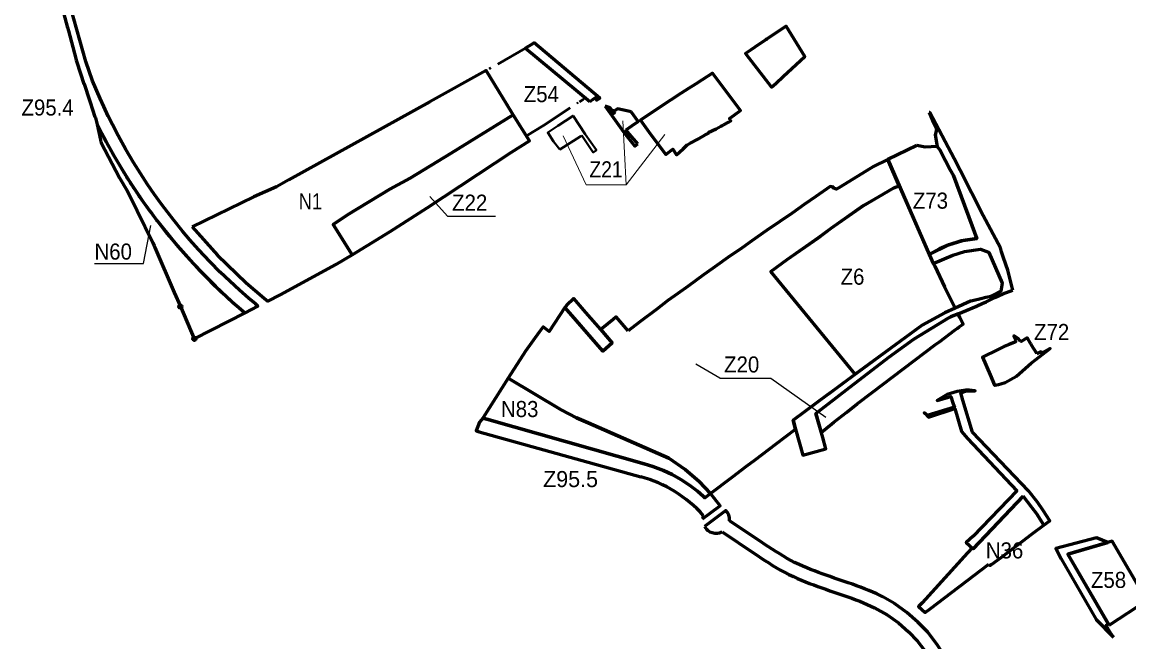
# Model space of a CAD drawing. Extents: x -650277 to -643422, y -1073980 to -1066720.
# Drawn here: x -649120 to -647467, y -1071620 to -1070696 of the extents above; entities that cross this region are included whole.
import ezdxf

# ---------------------------------------------------------------- set-up
doc = ezdxf.new("R2010")
doc.units = 0
doc.header["$LTSCALE"] = 9.6
doc.header["$PDMODE"] = 32
doc.header["$PDSIZE"] = 4.8
doc.linetypes.add('DOT_DASHED', pattern=[7.7, 5, -1.2, 0.3, -1.2])
for name, color, linetype, lineweight in [('1', 7, 'Continuous', 60), ('15', 7, 'Continuous', 60), ('18', 7, 'Continuous', 60), ('42', 7, 'Continuous', 60), ('60', 7, 'Continuous', 60), ('63', 7, 'Continuous', 25), ('7', 7, 'Continuous', 60), ('9', 7, 'Continuous', 60)]:
    doc.layers.add(name, color=color, linetype=linetype, lineweight=lineweight)

msp = doc.modelspace()

# ---------------------------------------------------------------- linework, layer by layer
at = {"layer": '1'}
for points in [[(-648032.601, -1070737.472), (-648039.82, -1070742.33), (-648000.85, -1070792.88), (-647994.63, -1070787.05), (-647982.89, -1070776.05), (-647976.97, -1070770.51), (-647964.21, -1070758.77), (-647951.11, -1070746.78), (-647979.17, -1070701.65), (-648008.28, -1070720.96), (-648009.29, -1070721.79), (-648019.49, -1070728.65)], [(-648540.7, -1070928.6), (-648571.14, -1070944.67), (-648634.07, -1070983.17), (-648655.76, -1070997.5), (-648627.39, -1071042.65), (-648605.3, -1071029.34), (-648570.23, -1071008.2), (-648515.46, -1070972.94), (-648389.33, -1070889.79), (-648362.519, -1070872.788), (-648386.587, -1070833.807), (-648479.18, -1070891.26)], [(-648215.08, -1071156.35), (-648232.8, -1071135.6), (-648237.46, -1071139.38), (-648245.49, -1071145.91), (-648256.04, -1071154.5), (-648238.84, -1071174.33), (-648253.126, -1071186.542), (-648292.587, -1071141.054), (-648309.41, -1071121.655), (-648333.002, -1071157.07), (-648341.943, -1071150.071), (-648347.949, -1071158.385), (-648368.48, -1071186.81), (-648394.104, -1071227.17), (-648315.127, -1071274.052), (-648292.406, -1071286.112), (-648274.918, -1071293.751), (-648154.21, -1071346.477), (-648130, -1071363), (-648109, -1071381), (-648091.92, -1071399.07), (-648060.01, -1071374.69), (-648038.18, -1071358.51), (-648025.39, -1071348.76), (-647994.31, -1071325.03), (-647965.26, -1071302.86), (-647966.226, -1071299.385), (-647968.896, -1071289.779), (-647916.208, -1071250.662), (-647895.959, -1071235.746), (-647875.939, -1071221.104), (-648001.922, -1071067.83), (-647977.41, -1071049.74), (-647930.96, -1071017.383), (-647912.11, -1071003.11), (-647864.29, -1070969.503), (-647818.33, -1070942.91), (-647810.243, -1070939.825), (-647827.527, -1070900.351), (-647848.89, -1070911.21), (-647897.76, -1070941.62), (-647904.13, -1070944.78), (-647909.42, -1070942.63), (-647908.63, -1070942.1), (-647913.45, -1070940.79), (-647934.9, -1070955.87), (-647952.01, -1070967.82), (-647970.19, -1070980.45), (-647988.81, -1070993.27), (-648008.34, -1071006.32), (-648030.24, -1071021.91), (-648044.82, -1071032.25), (-648051.48, -1071036.97), (-648062.53, -1071044.59), (-648085.73, -1071060.92), (-648097.61, -1071069.37), (-648102.55, -1071072.86), (-648125.53, -1071089.51), (-648141.12, -1071100.71), (-648155.77, -1071111.23), (-648172.48, -1071123.95), (-648197.57, -1071143.03)], [(-648001.922, -1071067.83), (-647977.41, -1071049.74), (-647930.7, -1071017.18), (-647911.838, -1071002.919), (-647864.03, -1070969.3), (-647864.03, -1070969.3), (-647818.33, -1070942.91), (-647810.243, -1070939.825), (-647759.52, -1071055.67), (-647757.19, -1071059.66), (-647742.64, -1071090.72), (-647726.74, -1071122.48), (-647742.35, -1071129.43), (-647775.982, -1071148.001), (-647775.982, -1071148.001), (-647875.939, -1071221.104)], [(-647756.03, -1071176.76), (-647750.34, -1071172.5), (-647726.56, -1071154.68), (-647723.79, -1071152.61), (-647720.85, -1071150.41), (-647714.71, -1071146.51), (-647719.73, -1071136.48), (-647722.51, -1071130.93), (-647732.58, -1071135.04), (-647733.38, -1071135.37), (-647737.027, -1071137.593), (-647761.366, -1071152.304), (-647788.66, -1071168.8), (-647826.56, -1071195.86), (-647889.22, -1071244.48), (-647915.6, -1071264.95), (-647934.6, -1071279.45), (-647926.69, -1071307.81), (-647910.73, -1071295.08), (-647907.92, -1071292.84), (-647888.77, -1071277.56), (-647873.25, -1071265.17), (-647850.956, -1071248.208)]]:
    msp.add_lwpolyline(points, close=True, dxfattribs=at)
at = {"layer": '1', "linetype": 'DOT_DASHED', "lineweight": 40}
msp.add_lwpolyline([(-648368.163, -1070734.376), (-648427.25, -1070767.95), (-648366.98, -1070865.44), (-648341.58, -1070849.98), (-648287.74, -1070814.32), (-648282.44, -1070810.84), (-648278.832, -1070808.761)], close=True, dxfattribs=at)
at = {"layer": '1'}
for points in [[(-648095.42, -1070860.3), (-648083.65, -1070854.89), (-648076.73, -1070851.07), (-648074.41, -1070849.79), (-648072.59, -1070848.79), (-648065.35, -1070844.8), (-648061.52, -1070842.68), (-648063.76, -1070839.49), (-648056.61, -1070834.26), (-648047.17, -1070827.35), (-648089.27, -1070771.57), (-648104.78, -1070781.65), (-648114.77, -1070788.08), (-648125.2, -1070794.79), (-648136.08, -1070801.79)], [(-648136.08, -1070801.79), (-648151.77, -1070812.11), (-648167.6, -1070822.53), (-648196.65, -1070841.7), (-648181.75, -1070862.74), (-648158.58, -1070892.98), (-648148.34, -1070884.92), (-648142.79, -1070893.78), (-648133.14, -1070884.6), (-648127, -1070878.75), (-648122.72, -1070876.44), (-648111.24, -1070870.11), (-648099.85, -1070863.82), (-648094.9, -1070861.09), (-648095.42, -1070860.3)], [(-648237.46, -1070829.68), (-648241.96, -1070823.46), (-648249.5, -1070821.08)], [(-648249.5, -1070821.08), (-648222.158, -1070859.221), (-648217.1, -1070865.56), (-648205.18, -1070880.5), (-648200.86, -1070877.05)], [(-648210.517, -1070829.445), (-648221.58, -1070827.03), (-648231.22, -1070824.92), (-648237.46, -1070829.68)], [(-648218.11, -1070856.44), (-648209.37, -1070850.44), (-648200.17, -1070844.094), (-648210.517, -1070829.445)], [(-648200.86, -1070877.05), (-648212.94, -1070862.74), (-648217.85, -1070856.93), (-648218.11, -1070856.44)]]:
    msp.add_lwpolyline(points, dxfattribs=at)
at = {"layer": '1', "lineweight": 40}
for points in [[(-648284.02, -1070864.91), (-648267.24, -1070889.9), (-648262.4, -1070886.58), (-648279.39, -1070862.98), (-648297.39, -1070835.36), (-648320.02, -1070850.16), (-648335.19, -1070860.49), (-648326.41, -1070873.55), (-648317.14, -1070885.48)], [(-648317.14, -1070885.48), (-648285.72, -1070865.96), (-648284.02, -1070864.91)]]:
    msp.add_lwpolyline(points, dxfattribs=at)
at = {"layer": '1', "lineweight": 13}
for points in [[(-648223, -1070843), (-648217.945, -1070938.322), (-648277.841, -1070938.322), (-648311.985, -1070865.23)], [(-648277.841, -1070938.322), (-648217.945, -1070938.322), (-648160.135, -1070863.066)]]:
    msp.add_lwpolyline(points, dxfattribs=at)
at = {"layer": '1'}
msp.add_point((-648237.46, -1070829.68), dxfattribs=at)
at = {"layer": '15'}
msp.add_line((-648272.453, -1070814.072), (-648271.1, -1070813.17), dxfattribs=at)
for points in [[(-648271.1, -1070813.17), (-648267.8, -1070810.96), (-648264.38, -1070808.66), (-648262.15, -1070811.96), (-648257.61, -1070808.91), (-648355.275, -1070726.455), (-648360.83, -1070729.87), (-648366.739, -1070733.501), (-648368.163, -1070734.376), (-648272.453, -1070814.072)], [(-647659.01, -1071032.66), (-647685.1, -1070983.93), (-647719.06, -1070916.45), (-647728.35, -1070899.11), (-647764.84, -1070830.47), (-647765.72, -1070830.64)], [(-647765.72, -1070830.64), (-647759.08, -1070845.74), (-647755.87, -1070853.02), (-647754.6, -1070856.11), (-647756.45, -1070863.95), (-647753.81, -1070881.3)], [(-647753.81, -1070881.3), (-647749.75, -1070886.1), (-647734.48, -1070915.94), (-647729.27, -1070924.35), (-647701.45, -1070999.4)], [(-647701.45, -1070999.4), (-647694.54, -1071018.549), (-647718, -1071022), (-647736, -1071028), (-647750, -1071034), (-647765.408, -1071042.223), (-647759.52, -1071055.67), (-647730.17, -1071043.21), (-647712.74, -1071037.99), (-647688.9, -1071034.18), (-647676.96, -1071039.014)], [(-647676.96, -1071039.014), (-647676.9, -1071039.03), (-647676.45, -1071039.22), (-647656.443, -1071085.369), (-647658.55, -1071097.02), (-647669.02, -1071102.33), (-647667.35, -1071106.38), (-647655.47, -1071100.98), (-647640.727, -1071095.819)], [(-647640.727, -1071095.819), (-647648.106, -1071065.551), (-647654.747, -1071047.095), (-647657.699, -1071038.232), (-647659.01, -1071032.66)], [(-647498.271, -1071593.544), (-647558.654, -1071489.738), (-647498.8, -1071471.94), (-647515.87, -1071465.25), (-647576.471, -1071481.091), (-647568.35, -1071496.656), (-647516.376, -1071586.89), (-647490.561, -1071613.609)], [(-647490.561, -1071613.609), (-647493.6, -1071608.5), (-647501.11, -1071595.45), (-647498.271, -1071593.544)]]:
    msp.add_lwpolyline(points, dxfattribs=at)
for points in [[(-647734.48, -1070915.94), (-647741.21, -1070902.78), (-647749.75, -1070886.1)], [(-647826.56, -1071195.86), (-647788.66, -1071168.8), (-647761.366, -1071152.304), (-647737.027, -1071137.593), (-647733.38, -1071135.37), (-647732.58, -1071135.04), (-647722.51, -1071130.93), (-647716.51, -1071128.48), (-647695.08, -1071119.72), (-647685.55, -1071115.14), (-647684.15, -1071114.47), (-647680.64, -1071112.77), (-647667.35, -1071106.38), (-647669.02, -1071102.33), (-647674.17, -1071104.97), (-647675.64, -1071105.71), (-647680.82, -1071106.54), (-647688.45, -1071108.38), (-647701.04, -1071111.41), (-647703.96, -1071112.11), (-647726.74, -1071122.48), (-647742.35, -1071129.43), (-647775.982, -1071148.001), (-647895.959, -1071235.746), (-647916.161, -1071250.628), (-647916.208, -1071250.662), (-647968.896, -1071289.779), (-647965.26, -1071302.86), (-647954.38, -1071342), (-647934.51, -1071336.37), (-647919.88, -1071332.23), (-647924.53, -1071315.55), (-647934.6, -1071279.45), (-647915.6, -1071264.95), (-647889.22, -1071244.48)], [(-648238.84, -1071174.33), (-648256.04, -1071154.5), (-648278.39, -1071128.74), (-648296.34, -1071108.04), (-648307.33, -1071118.47), (-648309.41, -1071121.655), (-648292.587, -1071141.054), (-648270.236, -1071166.815), (-648253.126, -1071186.542)], [(-647625.428, -1071403.267), (-647612.269, -1071419.742), (-647605.292, -1071428.816), (-647594.43, -1071446.543), (-647585.273, -1071440.044), (-647595.335, -1071424.564), (-647603.9, -1071412.1), (-647617.49, -1071394.901), (-647700.816, -1071307.512), (-647715.355, -1071259.885), (-647718.342, -1071248.972), (-647711.447, -1071246.332), (-647696.81, -1071245.79), (-647705.59, -1071245.08), (-647710.94, -1071244.65), (-647723.57, -1071246.66), (-647738.56, -1071251.13), (-647753.647, -1071260.178), (-647733.15, -1071254.081), (-647729.795, -1071265.066), (-647728.006, -1071269.975), (-647768.445, -1071282.6), (-647772.97, -1071278.43), (-647772.07, -1071279.33), (-647766.35, -1071285.11), (-647727.368, -1071272.362), (-647717.363, -1071306.29), (-647708.429, -1071316.821), (-647634.524, -1071394.901), (-647700.078, -1071462.96), (-647710.546, -1071472.023), (-647699.767, -1071481.617)]]:
    msp.add_lwpolyline(points, close=True, dxfattribs=at)
at = {"layer": '18'}
for points in [[(-647783.95, -1070879.58), (-647827.363, -1070900.725), (-647765.408, -1071042.223), (-647736, -1071028), (-647715.488, -1071021.631)], [(-647783.95, -1070879.58), (-647827.363, -1070900.725), (-647765.408, -1071042.223), (-647736, -1071028), (-647715.488, -1071021.631)], [(-647715.488, -1071021.631), (-647694.54, -1071018.549), (-647701.45, -1070999.4), (-647729.27, -1070924.35), (-647734.48, -1070915.94), (-647749.75, -1070886.1), (-647753.81, -1070881.3), (-647771.47, -1070882.27), (-647783.95, -1070879.58)], [(-647715.488, -1071021.631), (-647694.54, -1071018.549), (-647701.45, -1070999.4), (-647729.27, -1070924.35), (-647734.48, -1070915.94), (-647749.75, -1070886.1), (-647753.81, -1070881.3), (-647771.47, -1070882.27), (-647783.95, -1070879.58)]]:
    msp.add_lwpolyline(points, dxfattribs=at)
at = {"layer": '42'}
for p, q in [((-648883.73, -1071120.13), (-648862.97, -1071168.09)), ((-648862.97, -1071168.09), (-648787.207, -1071129.363))]:
    msp.add_line(p, q, dxfattribs=at)
for points in [[(-649002.97, -1070857.609), (-649007.885, -1070848.153), (-649003.1, -1070871.35), (-649002.82, -1070872.69), (-649002.62, -1070873.69), (-649002.15, -1070875.96), (-648974.4, -1070927.77), (-648963.5, -1070946.45), (-648959.92, -1070953.73), (-648948.29, -1070977.37), (-648924.92, -1071024.89), (-648922.98, -1071029.49), (-648921.87, -1071032.04), (-648892.82, -1071099.15), (-648883.73, -1071120.13)], [(-648994.42, -1070874.053), (-648994.464, -1070873.974), (-648994.52, -1070873.867)], [(-648982.403, -1070895.812), (-648982.467, -1070895.704), (-648982.524, -1070895.601)], [(-648970.64, -1070915.778), (-648970.712, -1070915.663), (-648970.771, -1070915.564)], [(-648960.194, -1070932.542), (-648960.268, -1070932.429), (-648960.34, -1070932.313)], [(-648949.345, -1070949.096), (-648949.389, -1070949.031), (-648949.428, -1070948.972)], [(-648939.179, -1070963.89), (-648939.232, -1070963.818), (-648939.33, -1070963.675)], [(-648918.464, -1070992.141), (-648918.601, -1070991.969), (-648918.737, -1070991.784)], [(-648292.406, -1071286.112), (-648315.127, -1071274.052), (-648394.104, -1071227.17), (-648432.093, -1071286.645)], [(-648432.093, -1071286.645), (-648426.18, -1071288.32), (-648191.25, -1071354.858)], [(-648091.92, -1071399.07), (-648109, -1071381), (-648130, -1071363), (-648154.21, -1071346.477), (-648274.918, -1071293.751), (-648292.406, -1071286.112)], [(-648191.25, -1071354.858), (-648178.158, -1071358.781), (-648162.084, -1071364.918), (-648149.571, -1071370.788), (-648136.263, -1071378.194), (-648123.313, -1071386.696), (-648111.646, -1071395.618), (-648103.268, -1071402.88), (-648100.438, -1071405.517), (-648091.92, -1071399.07)], [(-647625.428, -1071403.267), (-647699.767, -1071481.617), (-647701.415, -1071480.15), (-647708.18, -1071487.57), (-647776.13, -1071562.1)], [(-647676.51, -1071504.34), (-647674.28, -1071506.59), (-647656.27, -1071493.04), (-647626.7, -1071470.46), (-647611.82, -1071459.38), (-647594.43, -1071446.543), (-647605.292, -1071428.816), (-647612.269, -1071419.742), (-647625.428, -1071403.267)], [(-647776.13, -1071562.1), (-647781.31, -1071567.79), (-647771.717, -1071576.551), (-647764.23, -1071571.01), (-647676.51, -1071504.34)]]:
    msp.add_lwpolyline(points, dxfattribs=at)
for start, end in [(206.85611, 208.07207), (208.08607, 209.71957), (209.73567, 211.25686), (211.27351, 212.56631), (212.58435, 213.8879), (213.89777, 215.07157), (215.08899, 217.38409), (217.41391, 230.04071)]:
    msp.add_arc((-648232.695, -1070467.567), 863.398, start, end, dxfattribs=at)
for p in [(-648883.73, -1071120.13), (-648862.97, -1071168.09)]:
    msp.add_point(p, dxfattribs=at)
at = {"layer": '60'}
for points in [[(-649068.65, -1070642.23), (-649054.31, -1070696.44), (-649052.77, -1070702.25), (-649052.44, -1070703.48), (-649051.03, -1070708.74), (-649040.03, -1070750.06), (-649039.38, -1070752.51), (-649039.06, -1070753.72), (-649038.51, -1070755.38), (-649027.74, -1070787.51), (-649027.64, -1070787.8), (-649019.48, -1070812.18), (-649018.48, -1070815.18), (-649011.24, -1070836.79), (-649010.67, -1070838.5), (-649007.885, -1070848.153), (-648994.464, -1070873.974), (-648982.467, -1070895.704), (-648970.712, -1070915.663), (-648960.268, -1070932.429), (-648949.389, -1070949.031), (-648939.232, -1070963.818), (-648918.601, -1070991.969), (-648896.068, -1071020.184), (-648886.874, -1071031.044), (-648874.793, -1071044.773), (-648863.847, -1071056.723), (-648851.175, -1071069.886), (-648838.696, -1071082.562), (-648823.087, -1071097.562), (-648816.379, -1071103.782), (-648806.239, -1071112.938), (-648797, -1071121), (-648790.23, -1071126.818), (-648787.207, -1071129.363), (-648767.824, -1071119.455), (-648771.725, -1071116.233), (-648781.806, -1071107.721), (-648795.407, -1071095.8), (-648824.292, -1071068.677), (-648839.273, -1071053.556), (-648856.883, -1071034.761), (-648869.629, -1071020.411), (-648880.44, -1071007.703), (-648894.164, -1070990.806), (-648902.714, -1070979.812), (-648912.396, -1070966.893), (-648922.92, -1070952.242), (-648932.78, -1070937.887), (-648943.414, -1070921.659), (-648953.605, -1070905.299), (-648965.093, -1070885.794), (-648976.834, -1070864.527), (-648985.145, -1070848.538), (-648991.386, -1070835.954), (-648998.132, -1070821.723), (-649003.641, -1070809.566), (-649014.888, -1070782.994), (-649025.129, -1070754.377), (-649047.11, -1070674.743)], [(-648103.894, -1071436.836), (-648079.108, -1071418.564), (-648077.53, -1071417.4), (-648091.92, -1071399.07), (-648100.438, -1071405.517), (-648103.268, -1071402.88), (-648111.646, -1071395.618), (-648123.313, -1071386.696), (-648136.263, -1071378.194), (-648149.571, -1071370.788), (-648162.084, -1071364.918), (-648178.158, -1071358.781), (-648191.25, -1071354.858), (-648426.18, -1071288.32), (-648432.093, -1071286.645), (-648437.16, -1071292.53), (-648442.191, -1071305.453), (-648437.454, -1071306.778), (-648196.236, -1071374.226)], [(-648063.593, -1071439.723), (-648063.862, -1071435.078), (-648064.838, -1071431.28), (-648066.623, -1071427.592), (-648069.022, -1071424.443), (-648101.203, -1071448.31)], [(-648101.203, -1071448.31), (-648098.259, -1071452.196), (-648096.014, -1071454.192), (-648093.059, -1071456.066), (-648089.539, -1071457.489), (-648085.585, -1071458.248), (-648081.642, -1071458.215), (-648078.539, -1071457.636), (-648074.86, -1071456.248)], [(-647834.953, -1071553.406), (-647837.929, -1071551.872), (-647843.891, -1071549), (-647849.898, -1071546.282), (-647855.937, -1071543.707), (-647861.998, -1071541.254), (-647868.073, -1071538.911), (-647874.155, -1071536.658), (-647880.233, -1071534.48), (-647886.305, -1071532.36), (-647892.363, -1071530.282), (-647901.28, -1071527.249), (-647907.294, -1071525.204), (-647913.282, -1071523.152), (-647919.238, -1071521.081), (-647925.157, -1071518.976), (-647931.035, -1071516.824), (-647936.866, -1071514.613), (-647942.644, -1071512.329), (-647948.363, -1071509.96), (-647954.016, -1071507.496), (-647959.792, -1071504.833), (-647966.547, -1071501.883), (-647972.035, -1071499.009), (-647977.67, -1071495.885), (-647983.266, -1071492.628), (-647988.829, -1071489.259), (-647994.366, -1071485.79), (-647999.887, -1071482.241), (-648005.399, -1071478.627), (-648010.917, -1071474.963), (-648016.446, -1071471.268), (-648063.593, -1071439.723)], [(-648074.86, -1071456.248), (-648027.562, -1071487.894), (-648022.005, -1071491.607), (-648016.415, -1071495.321), (-648010.777, -1071499.017), (-648005.082, -1071502.678), (-647999.319, -1071506.287), (-647993.478, -1071509.826), (-647987.55, -1071513.275), (-647981.525, -1071516.615), (-647975.201, -1071519.929), (-647967.982, -1071523.081), (-647962.2, -1071525.746), (-647956.187, -1071528.368), (-647950.146, -1071530.869), (-647944.088, -1071533.263), (-647938.019, -1071535.566), (-647931.945, -1071537.788), (-647925.874, -1071539.949), (-647919.808, -1071542.058), (-647913.756, -1071544.132), (-647907.72, -1071546.185), (-647898.827, -1071549.208), (-647892.847, -1071551.26), (-647886.903, -1071553.336), (-647881.001, -1071555.45), (-647875.147, -1071557.619), (-647869.348, -1071559.856), (-647863.611, -1071562.177), (-647857.944, -1071564.594), (-647847.103, -1071569.497)], [(-647725.629, -1071678.373), (-647735.352, -1071657.117), (-647741.34, -1071644.028), (-647753.065, -1071625.201), (-647767.784, -1071606.225), (-647782.408, -1071590.847), (-647798.911, -1071576.526), (-647817.375, -1071563.458), (-647834.953, -1071553.406)], [(-647847.103, -1071569.497), (-647828.141, -1071580.34), (-647811.272, -1071592.28), (-647796.24, -1071605.324), (-647782.97, -1071619.278)], [(-647782.97, -1071619.278), (-647769.498, -1071636.647), (-647758.994, -1071653.513), (-647743.48, -1071687.426), (-647611.514, -1071974.086)]]:
    msp.add_lwpolyline(points, dxfattribs=at)
for centre, radius, start, end in [((-648244.965, -1071557.871), 190, 41.59858, 75.13936), ((-648083.781, -1071438.172), 20.157, 161.35794, 176.20098)]:
    msp.add_arc(centre, radius, start, end, dxfattribs=at)
at = {"layer": '63'}
msp.add_line((-648078, -1071227), (-648114, -1071206), dxfattribs=at)
for points in [[(-648511, -1070956), (-648485, -1070985), (-648413, -1070985)], [(-649012, -1071056), (-648939, -1071056), (-648928, -1070999)], [(-648078, -1071227), (-648002, -1071227), (-647920, -1071285)], [(-648078, -1071227), (-648002, -1071227), (-647920, -1071285)]]:
    msp.add_lwpolyline(points, dxfattribs=at)
at = {"layer": '7'}
msp.add_lwpolyline([(-648866.341, -1071000.881), (-648828.353, -1071043.265), (-648785.386, -1071084.634), (-648758.423, -1071107.756), (-648752.967, -1071111.861), (-648734.849, -1071102.599), (-648651.375, -1071057.109), (-648627.39, -1071042.65), (-648655.76, -1070997.5), (-648634.07, -1070983.17), (-648571.14, -1070944.67), (-648540.7, -1070928.6), (-648479.18, -1070891.26), (-648386.587, -1070833.807), (-648396.611, -1070817.573), (-648407.667, -1070799.667), (-648427.25, -1070767.95), (-648511.09, -1070814.7), (-648721.54, -1070930.88), (-648740.25, -1070941.21), (-648774.23, -1070956.42)], close=True, dxfattribs=at)
at = {"layer": '9'}
for points in [[(-647635.93, -1071171.22), (-647637.87, -1071173.29), (-647646.09, -1071176.68), (-647653.85, -1071179.87), (-647662.634, -1071183.968)], [(-647629.09, -1071172.4), (-647632.93, -1071167.71), (-647638.46, -1071163.89), (-647639.32, -1071164.22), (-647635.93, -1071171.22)], [(-647612.695, -1071177.542), (-647613.91, -1071175.57), (-647614.732, -1071174.222), (-647618.446, -1071168.166), (-647618.469, -1071168.129), (-647618.77, -1071167.64), (-647619.264, -1071166.832), (-647619.34, -1071166.709), (-647628.39, -1071172.05), (-647629.09, -1071172.4)], [(-647662.634, -1071183.968), (-647686.01, -1071195.35), (-647686.01, -1071195.35)], [(-647674.6, -1071221.71), (-647668.226, -1071237.571), (-647667.77, -1071237.5), (-647661.99, -1071236.62), (-647658.78, -1071235.63), (-647651.93, -1071233.57), (-647635.17, -1071224.18), (-647613.09, -1071204.33), (-647607.02, -1071199.34), (-647584.92, -1071182.54), (-647597.164, -1071189.857), (-647598.215, -1071187.608), (-647604.576, -1071190.781)], [(-647604.576, -1071190.781), (-647604.888, -1071190.272), (-647612.695, -1071177.542)], [(-647686.01, -1071195.35), (-647686.01, -1071195.35), (-647674.6, -1071221.71)]]:
    msp.add_lwpolyline(points, dxfattribs=at)
msp.add_lwpolyline([(-647497.04, -1071595.66), (-647440.67, -1071558.93), (-647492.3, -1071470), (-647495.85, -1071471.06), (-647558.654, -1071489.738)], close=True, dxfattribs=at)

# ---------------------------------------------------------------- texts
at = {"layer": '1'}
for s, width, p in [('Z54', 0.95, (-648371, -1070815)), ('Z21', 0.9, (-648272.998, -1070927.282))]:
    msp.add_text(s, height=24, dxfattribs=dict(at, width=width)).set_placement(p)
at = {"layer": '63'}
for s, width, p in [('Z95.4', 0.95, (-649121, -1070835)), ('N1', 0.85, (-648707, -1070975)), ('Z22', 0.95, (-648478, -1070977)), ('Z73', 0.95, (-647790, -1070974)), ('N60', 0.95, (-649012, -1071050)), ('Z6', 0.95, (-647897.847, -1071087.452)), ('Z6', 0.95, (-647897.847, -1071087.452)), ('Z72', 0.95, (-647609, -1071170)), ('Z20', 0.95, (-648071.847, -1071218.452)), ('Z20', 0.95, (-648071.847, -1071218.452)), ('N83', 0.95, (-648405, -1071285)), ('N36', 0.95, (-647681, -1071496)), ('Z58', 0.95, (-647524, -1071540))]:
    msp.add_text(s, height=24, dxfattribs=dict(at, width=width)).set_placement(p)
msp.add_text('Z95.5', height=24, dxfattribs=at).set_placement((-648342.123, -1071389.545))

doc.saveas('drawing.dxf')
